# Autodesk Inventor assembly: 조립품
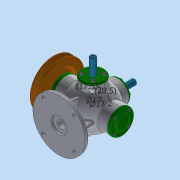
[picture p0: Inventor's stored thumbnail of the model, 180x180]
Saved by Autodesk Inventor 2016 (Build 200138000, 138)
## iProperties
Created: 2019-11
Part Number: 조립품
Material: 일반
Document SubType Name: Assembly
Designer: user
Mass: 3778.22 g
Surface Area: 2410.89 cm^2
Volume: 904.615 cm^3
Density: 4.17661 g/cm^3
Author: user
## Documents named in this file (17)
- C:\Users\user\Desktop\391120V1006\조립품.iam
- C:\Users\user\Desktop\391120V1006\V-벨트풀리.ipt
- C:\Users\user\Desktop\391120V1006\너트 M8x1.ipt
- C:\Users\user\Desktop\391120V1006\뒤커버.ipt
- C:\Users\user\Desktop\391120V1006\베어링 6202.ipt
- C:\Users\user\Desktop\391120V1006\본체.ipt
- C:\Users\user\Desktop\391120V1006\본체커버.ipt
- C:\Users\user\Desktop\391120V1006\볼트 M4.ipt
- C:\Users\user\Desktop\391120V1006\스프링 1.ipt
- C:\Users\user\Desktop\391120V1006\스프링2.ipt
- C:\Users\user\Desktop\391120V1006\슬라이드 커버.ipt
- C:\Users\user\Desktop\391120V1006\슬라이드.ipt
- C:\Users\user\Desktop\391120V1006\앞커버.ipt
- C:\Users\user\Desktop\391120V1006\오일 실.ipt
- C:\Users\user\Desktop\391120V1006\와셔 8x17.ipt
- C:\Users\user\Desktop\391120V1006\축.ipt
- C:\Users\user\Desktop\391120V1006\키 4x4.ipt
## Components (1 placed, 1 different names)
1. V-벨트풀리:1
